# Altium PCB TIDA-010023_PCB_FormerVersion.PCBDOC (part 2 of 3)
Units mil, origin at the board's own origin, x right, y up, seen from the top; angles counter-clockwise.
Board outline 4724.44 x 3937.01 mil, 2 copper layers (Top Layer, Bottom Layer), stack 62 mil thick; 263 components, 126 nets, 611 pads, 186 vias.
Unrouted connection lines stored in the file: 58.
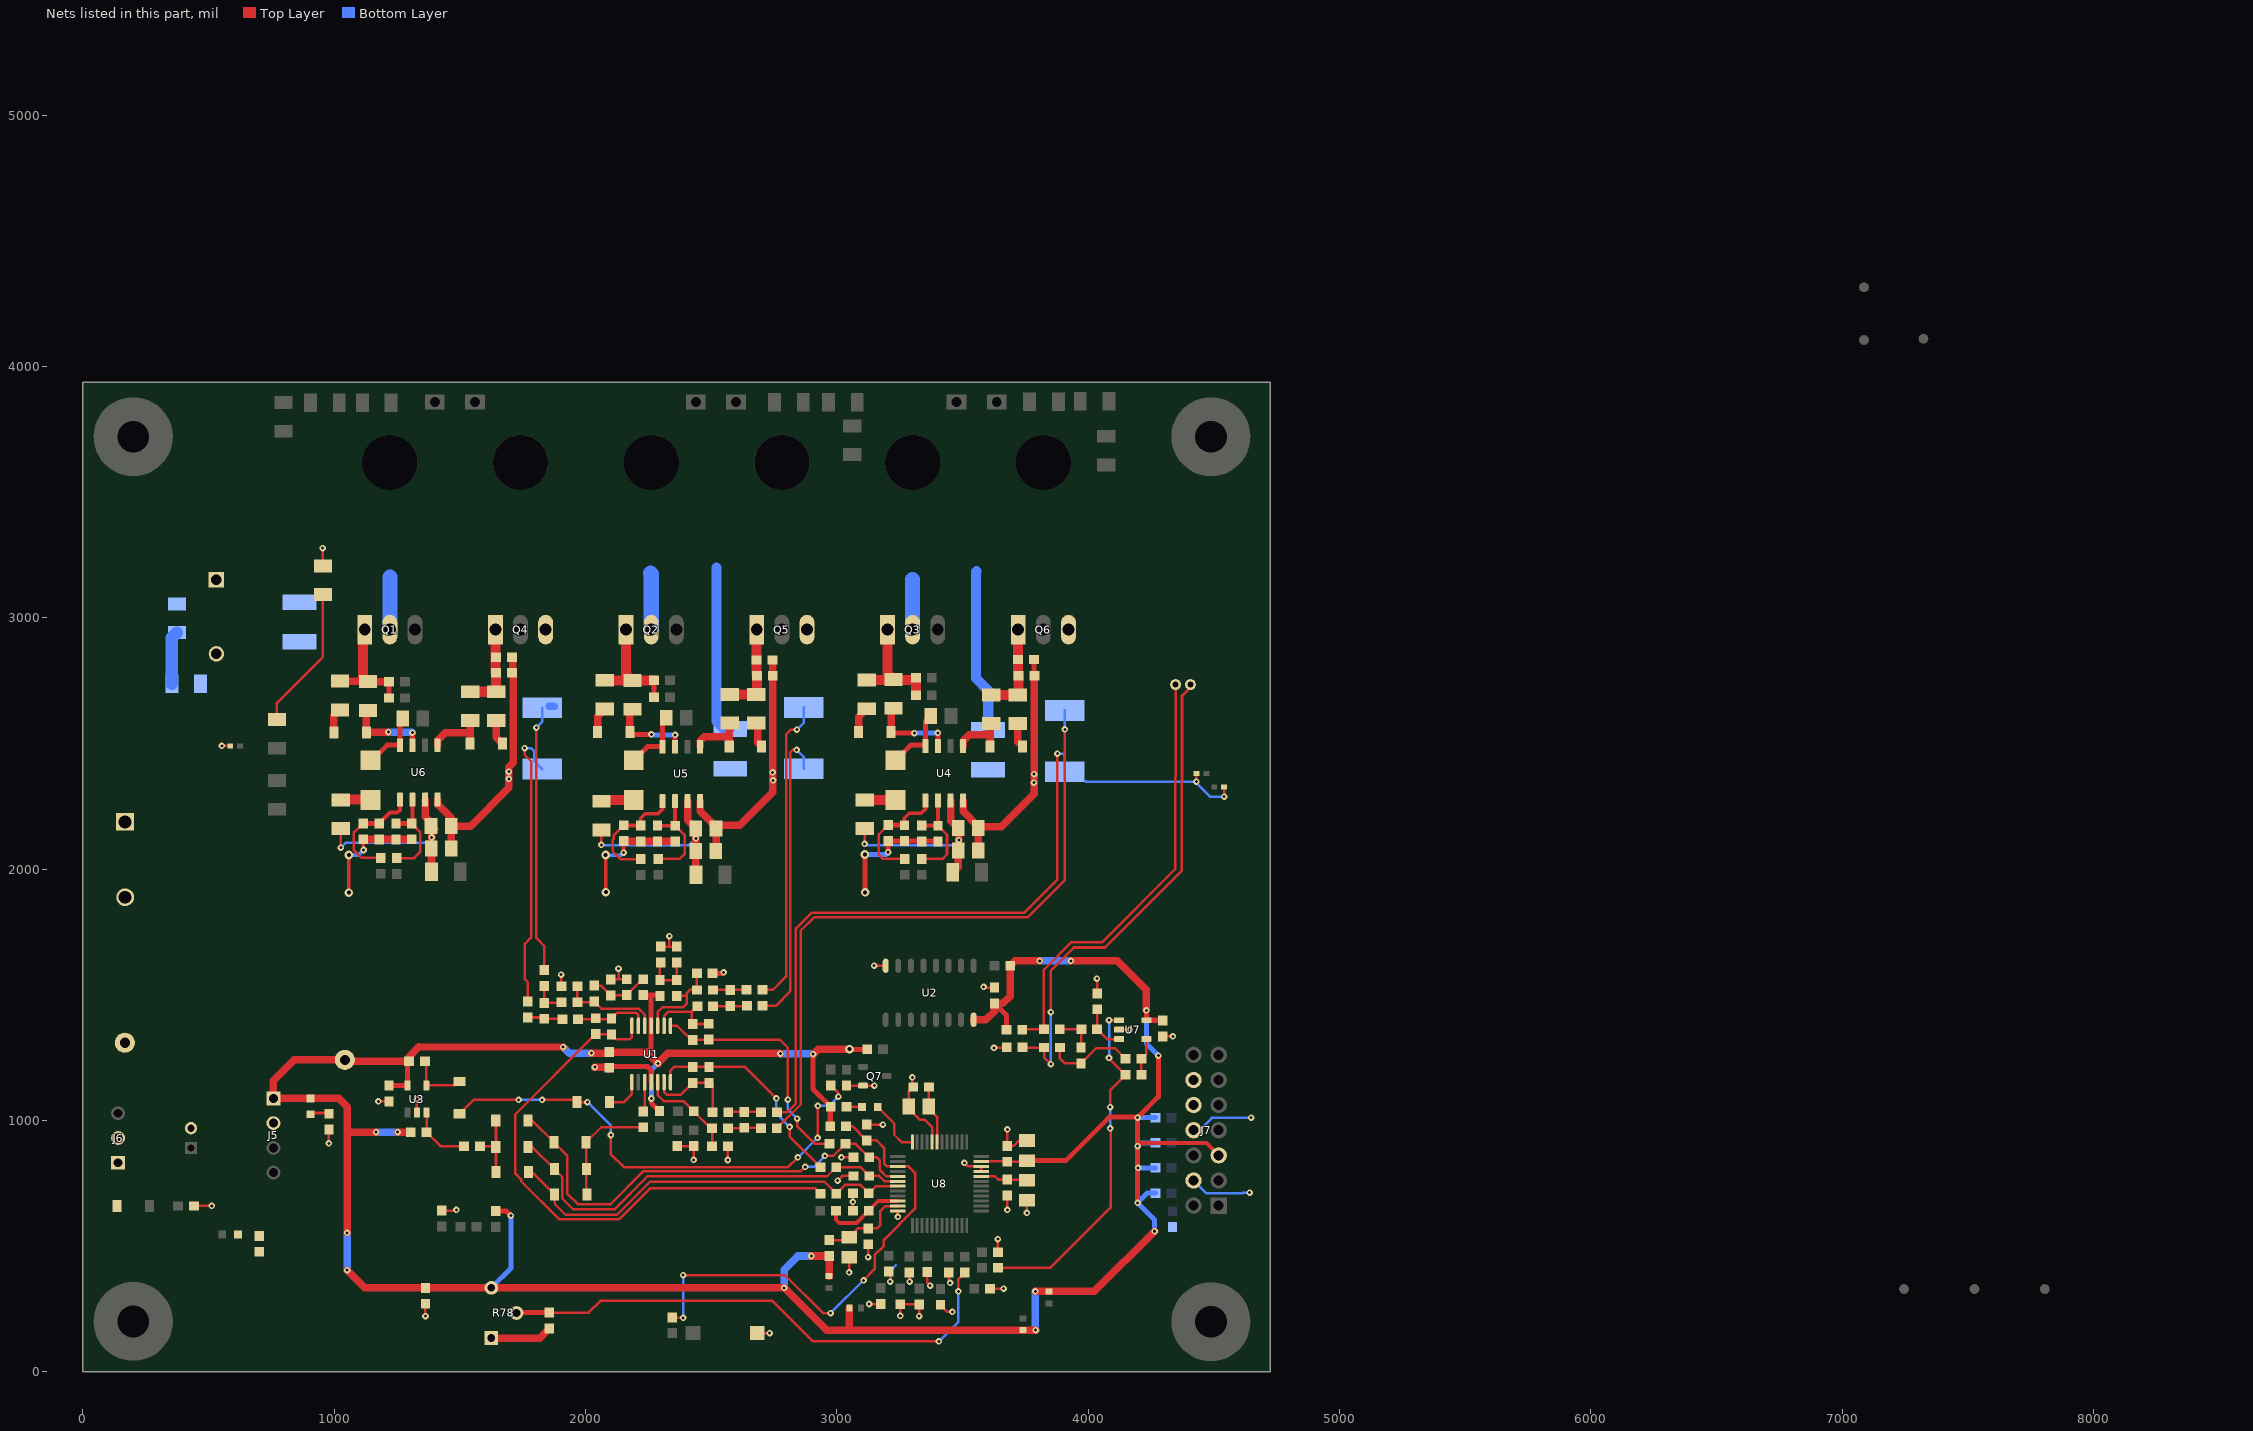
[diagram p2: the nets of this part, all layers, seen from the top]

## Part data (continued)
H1 H2 H3 H4: "Machine Screw, Round, #4-40 x 1/4, Nylon, Philips panhead", DigiKeyPartNumber=H542-ND, Manufacturer="B&F Fastener Supply"
H11 H12 H13 H14: "Standoff, Hex, 0.5\"L #4-40 Nylon", Alternate Manufacturer=-, Manufacturer=Keystone, Supplier Part Number 1=1902CK-ND
J1 J2 J3: "Header, 3.96 mm, 2x1, Tin, TH", Manufacturer="JST Manufacturing", Supplier Part Number 1=455-1639-ND
J4: library part 1707027, "TERMINAL BLOCK 7.50MM 2POS PCB", Color=Green, Current_A=16, Manufacturer="On Shore Technology Inc.", Supplier Part Number 1=ED2730-ND, Voltage_V=1000
J5: "Header (Shrouded), 2.5mm, 4x1, Tin, TH", Color=White, Current_A=3, Manufacturer="JST Manufacturing", Supplier Part Number 1=455-2249-ND, Voltage_V=250
J6: library part B2B-XH-A(LF)(SN), "Header (Shrouded), 2.5mm, 2x1, Tin, TH", Color=White, Current_A=3, Manufacturer="JST Manufacturing", Supplier Part Number 1=455-2247-ND, Voltage_V=250
J7: "Header, 100mil, 7x2, Tin, TH", Color=Black, Current_A=3, Manufacturer="Sullins Connector Solutions", Supplier Part Number 1=S2012E-07-ND, Voltage_V=1800
Logo_TI: library part TI_Logo, "Texas Instrument Corporate Signature"
Pb: library part Pb-Free
Pb_Free: library part ESD_Susceptible, "ESD Susceptible Symbol"
Q1 Q2 Q3 Q4 Q5 Q6: library part "IXYP15N65C3D1, IXYS", "Transistor, IGBT, 650 V, 38 A, TO-220AB", Manufacturer=IXYS, PartNumber=IXYP15N65C3D1, Supplier Part Number 1=IXYP15N65C3D1-ND, Value1="38 A"
Q7: library part "MMBT2222A, Fairchild Semiconductor", "Transistor, NPN, 40 V, 0.15 A, SOT-23", Manufacturer="Fairchild Semiconductor", Supplier Part Number 1=MMBT2222AFSCT-ND, Value1="0.15 A", Value2=300
R1 R13 R23: "RES, 4.99 k, 0.1%, 0.1 W, 0603", Manufacturer="Yageo America", Power_W=0.1, TempCo="25 ppm/C", Value1=0.1%, Value2=0.1W, Value_Code=4k99, ValueDisplayed=1.91k
R2 R14 R24: "RES, 4.99 k, 0.1%, 0.1 W, 0603", Manufacturer="Yageo America", Power_W=0.1, TempCo="25 ppm/C", Value1=0.1%, Value2=0.1W, Value_Code=4k99, ValueDisplayed=2k
R3 R9 R15 R22 R25 R29: "RES, 4.99 k, 0.1%, 0.1 W, 0603", Manufacturer="Yageo America", Power_W=0.1, TempCo="25 ppm/C", Value1=0.1%, Value2=0.1W, Value_Code=4k99, ValueDisplayed=40.2k
R4 R16 R26 R120: "RES, 100, 1%, 0.1 W, 0603", Manufacturer=Vishay-Dale, Power_W=0.1, Supplier Part Number 1=541-100HCT-ND, TempCo="100 ppm/C", Tolerance_%=1, Value1=1%, Value2=0.1W, Value_Code=100R, ValueDisplayed=47
R5 R7 R17 R21 R27 R28: library part RG1608P-101-B-T5, "RES, 100, 0.1%, 0.1 W, 0603", Manufacturer="Susumu Co Ltd", Power_W=0.1, Supplier Part Number 1=RG16P100BCT-ND, TempCo="25 ppm/C", Value1=0.1%, Value2=0.1W, Value_Code=100R, ValueDisplayed=1.91k
R6 R11: "RES, 10.0 k, 1%, 0.1 W, 0603", Manufacturer=Vishay-Dale, Power_W=0.1, Supplier Part Number 1=541-10.0KHCT-ND, TempCo="100 ppm/C", Tolerance_%=1, Value1=1%, Value2=0.1W, Value_Code=10k0, ValueDisplayed=0
R8 R66 R68 R70 R74 R79 R87: "RES, 100, 1%, 0.1 W, 0603", Manufacturer=Vishay-Dale, Power_W=0.1, Supplier Part Number 1=541-100HCT-ND, TempCo="100 ppm/C", Tolerance_%=1, Value1=1%, Value2=0.1W, Value_Code=100R, ValueDisplayed=100
R10: "RES, 10.0 k, 1%, 0.1 W, 0603", Manufacturer=Vishay-Dale, Power_W=0.1, Supplier Part Number 1=541-10.0KHCT-ND, TempCo="100 ppm/C", Tolerance_%=1, Value1=1%, Value2=0.1W, Value_Code=10k0, ValueDisplayed=100k
R12 R118 R119: "RES, 10.0 k, 1%, 0.1 W, 0603", Manufacturer=Vishay-Dale, Power_W=0.1, Supplier Part Number 1=541-10.0KHCT-ND, TempCo="100 ppm/C", Tolerance_%=1, Value1=1%, Value2=0.1W, Value_Code=10k0, ValueDisplayed=10k
R18 R63: "RES, 10.0 k, 1%, 0.1 W, 0603", Manufacturer=Vishay-Dale, Power_W=0.1, Supplier Part Number 1=541-10.0KHCT-ND, TempCo="100 ppm/C", Tolerance_%=1, Value1=1%, Value2=0.1W, Value_Code=10k0, ValueDisplayed=10.0k
R19: "RES, 21.5 k, 1%, 0.1 W, 0603", Manufacturer=Vishay-Dale, Power_W=0.1, Supplier Part Number 1=541-21.5KHCT-ND, TempCo="100 ppm/C", Tolerance_%=1, Value1=1%, Value2=0.1W, Value_Code=21k5, ValueDisplayed=21.5k
R20: library part CRCW060321K5FKEA, "RES, 21.5 k, 1%, 0.1 W, 0603", Manufacturer=Vishay-Dale, Power_W=0.1, Supplier Part Number 1=541-21.5KHCT-ND, TempCo="100 ppm/C", Tolerance_%=1, Value1=1%, Value2=0.1W, Value_Code=21k5, ValueDisplayed=10.0k
R30 R40 R59: "RES, 3.3 ohm, 5%, 0.25W, 1206", Manufacturer=Vishay-Dale, Power_W=0.25, Supplier Part Number 1=541-3.3ECT-ND, TempCo="200 ppm/C", Tolerance_%=5, Value1=5%, Value2=0.25W, Value_Code=3R30
R31 R41 R57 R60 R75: "RES, 12.0, 1%, 0.25 W, 1206", Manufacturer="Yageo America", Power_W=0.25, Supplier Part Number 1=311-12.0FRCT-ND, TempCo="100 ppm/C", Tolerance_%=1, Value1=1%, Value2=0.25W, Value_Code=12R0, ValueDisplayed=12.0
R32 R42 R61: "RES, 2.2, 1%, 0.1 W, 0603", Manufacturer="Yageo America", Power_W=0.1, Supplier Part Number 1=311-5.11HRCT-ND, TempCo="200 ppm/C", Tolerance_%=1, Value1=1%, Value2=0.1W, Value_Code=5R11, ValueDisplayed=2.2
R33 R37 R45 R55 R62 R72: "RES, 5, 1%, 0.25 W, 1206", Manufacturer=Vishay-Dale, Power_W=0.25, Supplier Part Number 1=541-6.04FFCT-ND, TempCo="100 ppm/C", Tolerance_%=1, Value1=1%, Value2=0.25W, Value_Code=6R04, ValueDisplayed=5.00
R34 R39 R49 R58 R64 R76: "RES, 20.0k ohm, 1%, 0.1W, 0603", Manufacturer=Vishay-Dale, Power_W=0.1, Supplier Part Number 1=541-20.0KHCT-ND, TempCo="100 ppm/C", Tolerance_%=1, Value1=1%, Value2=0.1W, Value_Code=20k0
R35 R36 R50 R54 R65 R71: "RES, 51.1, 1%, 0.1 W, 0603", Manufacturer=Vishay-Dale, Power_W=0.1, Supplier Part Number 1=541-51.1HCT-ND, TempCo="100 ppm/C", Tolerance_%=1, Value1=1%, Value2=0.1W, Value_Code=51R1, ValueDisplayed=49.9
R38: "RES, 12.0, 1%, 0.25 W, 1206", Manufacturer="Yageo America", Power_W=0.25, Supplier Part Number 1=311-12.0FRCT-ND, TempCo="100 ppm/C", Tolerance_%=1, Value1=1%, Value2=0.25W, Value_Code=12R0, ValueDisplayed=12.00
R43 R46 R47 R51 R53 R56: "RES, 0, 5%, 0.1 W, 0603", Manufacturer=Vishay-Dale, Power_W=0.1, Supplier Part Number 1=541-0.0GCT-ND, TempCo="200 ppm/C", Tolerance_%=5, Value1=5%, Value2=0.1W, Value_Code=0000, ValueDisplayed=100
R44 R48 R52: "RES, 0.005, 1%, 3 W, AEC-Q200 Grade 0, 2512", Manufacturer=Bourns, Power_W=3, Supplier Part Number 1=CRE2512-FZ-R005E-3CT-ND, TempCo="75 ppm/C", Tolerance_%=1, Value1=1%, Value2=3W, Value_Code=5L000, ValueDisplayed=0.005
R67 R69: "RES, 1.00 k, 1%, 0.1 W, 0603", Manufacturer=Vishay-Dale, Power_W=0.1, Supplier Part Number 1=541-1.00KHCT-ND, TempCo="100 ppm/C", Tolerance_%=1, Value1=1%, Value2=0.1W, Value_Code=1k00, ValueDisplayed=1.91k
R73 R77: "RES, 1.00 k, 1%, 0.1 W, 0603", Manufacturer=Vishay-Dale, Power_W=0.1, Supplier Part Number 1=541-1.00KHCT-ND, TempCo="100 ppm/C", Tolerance_%=1, Value1=1%, Value2=0.1W, Value_Code=1k00, ValueDisplayed=2.55k
R78: "TRIMMER, 20k ohm, 0.5W, TH", Manufacturer=Bourns, Supplier Part Number 1=3386P-203LF-ND
R80 R83: "RES, 300 k, 5%, 0.25 W, 1206", Manufacturer=Vishay-Dale, Power_W=0.25, Supplier Part Number 1=541-300KECT-ND, TempCo="200 ppm/C", Tolerance_%=5, Value1=5%, Value2=0.25W, Value_Code=300k
R81: "RES, 1.00 M, 1%, 0.1 W, 0603", Manufacturer=Vishay-Dale, Power_W=0.1, Supplier Part Number 1=541-1.00MHCT-ND, TempCo="100 ppm/C", Tolerance_%=1, Value1=1%, Value2=0.1W, Value_Code=1M00, ValueDisplayed=1.00M
R82 R85: "RES, 1.00 k, 1%, 0.1 W, 0603", Manufacturer=Vishay-Dale, Power_W=0.1, Supplier Part Number 1=541-1.00KHCT-ND, TempCo="100 ppm/C", Tolerance_%=1, Value1=1%, Value2=0.1W, Value_Code=1k00, ValueDisplayed=1.00k
R84: "RES, 4.99 k, 1%, 0.1 W, 0603", Manufacturer=Bourns, Power_W=0.1, Supplier Part Number 1=CR0603-FX-4991ELFTR-ND, TempCo="100 ppm/C", Tolerance_%=1, Value1=1%, Value2=0.1W, Value_Code=4k99, ValueDisplayed=4.99k
R86 R99 R100 R101 R102 R103: "RES, 4.7 k, 5%, 0.1 W, 0603", Manufacturer=Vishay-Dale, Power_W=0.1, Supplier Part Number 1=541-4.7KGCT-ND, TempCo="200 ppm/C", Tolerance_%=5, Value1=5%, Value2=0.1W, Value_Code=4k70, ValueDisplayed=4.7k
R88: "RES, 0, 5%, 0.1 W, 0603", Manufacturer=Vishay-Dale, Power_W=0.1, Supplier Part Number 1=541-0.0GCT-ND, TempCo="200 ppm/C", Tolerance_%=5, Value1=5%, Value2=0.1W, Value_Code=0000, ValueDisplayed=0
R91 R92 R93 R94 R95 R96 R97 R98 R104 R105 R106 R107: "RES, 374 k, 1%, 0.25 W, 1206", Manufacturer="Yageo America", Power_W=0.25, Supplier Part Number 1=311-374KFRCT-ND, TempCo="100 ppm/C", Tolerance_%=1, Value1=1%, Value2=0.25W, Value_Code=374k
R108 R109 R110 R111: "RES, 9.09 k, 1%, 0.1 W, 0603", Manufacturer=Vishay-Dale, Power_W=0.1, Supplier Part Number 1=541-9.09KHCT-ND, TempCo="100 ppm/C", Tolerance_%=1, Value1=1%, Value2=0.1W, Value_Code=9k09, ValueDisplayed=9.09k
R112 R113 R114 R115 R116 R117: "RES, 51.1, 1%, 0.1 W, 0603", Manufacturer=Vishay-Dale, Power_W=0.1, Supplier Part Number 1=541-51.1HCT-ND, TempCo="100 ppm/C", Tolerance_%=1, Value1=1%, Value2=0.1W, Value_Code=51R1, ValueDisplayed=10k
RT1: library part NTCALUG03A103G, "Thermistor NTC, 10k ohm, 2%, NTC Thermistor, Mini Lug Sensor, Pitch 1.5mm", Manufacturer=Vishay-Bccomponents, Power_W=0.1, Supplier Part Number 1=BC2385-ND, Tolerance_%=2
S1: "Switch, Tactile, SPST, 12 V, SMD", CurrentRating_mA=50, Manufacturer="Wurth Elektronik", Supplier Part Number 1=1867991
TP1 TP2: "Test Point, Miniature, Red, TH", Color=Red, Manufacturer=Keystone, Supplier Part Number 1=36-5000-ND
U1: library part TLV2774AID, "Quad High-Slew-Rate Rail-to-Rail Output Operational Amplifier, 2.5 to 6 V, -40 to 125 degC, 14-pin SOIC (D0014A), Green (RoHS & no Sb/Br)", Alternate Manufacturer="Texas Instruments", Alternate PartNumber=Equivalent, PartNumber=TLV2774AIDA, Rating=Catalog, Total Supply Voltage(Max)(+5V is 5, +/-5V is 10)=6, Total Supply Voltage(Min)(+5V is 5, +/-5V is 10)=2.5
U2: "Hex Buffers And Line Drivers With 3-State Outputs, D0016A, LARGE T&R", Alternate Manufacturer="Texas Instruments", Alternate PartNumber=Equivalent, F @ Nom Voltage(Max)(Mhz)=110, Generic Part Number=SN74AHC367, ICC @ Nom Voltage(Max)(mA)=0.04, Operating Temperature Range(C)="-40 to 85", Rating=Catalog, tpd @ Nom Voltage(Max)(ns)=12.5,8.5, Voltage(Nom)(V)=3.3,5
U3: "2.2-V to 36-V, microPower Comparator, DBV0005A", Alternate Manufacturer="Texas Instruments", Alternate PartNumber=TLV1701AIDBVT
U4 U5 U6: "620-V High-Side Low-Side Gate Driver with 2.5A Peak Output and RobustDrive, D0008B (SOIC-8)", Alternate Manufacturer="Texas Instruments", Alternate PartNumber=UCC27712D
U7: library part LMV721IDBV, "1-MHz, Low-Power Operational Amplifier", Alternate Manufacturer="Texas Instruments", PartNumber=TLV6001IDBVT
U8: library part TMS320F2802XPTA, "IC, 32-Bit Piccolo Microcontrollers, xx MHz", Alternate Manufacturer=None, Manufacturer=TI, PartNumber=TMS320F28027FPTT
U9 U10 U11: "ESD in 0402 Package with 10 pF Capacitance and 6 V Breakdown, 1 Channel, -40 to +125 degC, 2-pin X2SON (DPY), Green (RoHS & no Sb/Br)", Alternate Manufacturer="Texas Instruments", Alternate PartNumber=Equivalent, Breakdown Voltage(Min)(V)=6, IO Capacitance(Typ)(pF)=10, Supplier Part Number 1=296-30406-2-ND
ZZ1: library part AssemblyNoteLabel, Alternate Manufacturer=-
ZZ2 ZZ3 ZZ4: library part AssemblyNote, Alternate Manufacturer=-

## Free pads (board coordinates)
  round 220 hole 220: 1(1221.18,3617.91) 1(1741.18,3617.91) 1(2261.18,3617.91) 1(2781.18,3617.91) 1(3301.18,3617.91) 1(3821.18,3617.91)

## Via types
v1: diameter 26, hole 12, Top Layer to Bottom Layer, 157 vias
v2: diameter 34, hole 16, Top Layer to Bottom Layer, 28 vias
v3: diameter 32, hole 18, Top Layer to Bottom Layer, 1 vias

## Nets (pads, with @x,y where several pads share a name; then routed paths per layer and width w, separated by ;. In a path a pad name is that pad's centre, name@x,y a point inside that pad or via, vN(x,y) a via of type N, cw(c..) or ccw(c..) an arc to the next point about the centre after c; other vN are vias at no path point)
+3.3VD: C1.1 C2.2 C8.1 C39.1 C49.2 C52.1 C53.1 D19.2 D22.1 D23.1 D24.1 D25.1 J5.1 J7.5 R1.2 R10.1 R12.2 R13.2 R18.2 R23.2 R63.1 R78.3 R82.2 R86.2 R88.2 R99.2 R100.2 R101.2 R102.2 R118.1 R119.1 TP2.1 U1.4 U2.16 U3.5 U7.5 U8.35 | length 12718.7
  Top Layer w10: U8.35@3574.1,836.7 3676.8,836.7 C52.1@3678,835.5 3751.5,835.5 C53.1@3756,840
  Top Layer w15: v1(4196,898) 4208,910 4470,910 J7.5@4519,861
  Top Layer w20: C8.1@1218,1138.5 1290.96,1138.5 U3.5@1291.6,1139.13 1291.6,1230.09 R12.2@1297.5,1236 ; R18.2@1643,639.5 1684.5,639.5 v1(1703,621) ; C1.1@2101.64,1277.42 C1.1@2103,1277.42 ; R1.2@2228.98,1498.7 2263,1498.7 ; 2243.5,1270.5 2260.98,1287.97 U1.4@2260.98,1376.4 2260.98,1496.69 2263,1498.7 ; v1(2261.98,1087.2) 2261.98,1068.7 R23.2@2293.98,1036.7 ; R13.2@2295.98,1495.7 2292.98,1498.7 2263,1498.7 ; v1(2905,1264) 2905,1124.5 R82.2@2975.5,1054 2973.5,1052 R86.2@2973.5,977 ; v2(3050,1284) 3051,1283 R119.1@3120.5,1283 R119.1@3119.5,1284 ; C2.2@3627,1465.5 3674.5,1418 R63.1@3674.5,1361 R63.1@3673.79,1361.72 ; C53.1@3756,840 3910,840 4083,1013 4194,1013 v1(4196,1011) ; v1(4196,672) v1(4196,898) v1(4196,1011) ; v1(4231,1438) 4231.13,1437.87 U7.5@4231.13,1398.6 4294.9,1398.6 C39.1@4296,1397.5 ; v1(4279,1258) 4279,1094 v1(4196,1011)
  Top Layer w30: D19.2@902.14,1087.64 J5.1@758,1087.64 758,1158 841,1241 TP2.1@1042,1241 1047,1236 R12.2@1297.5,1236 1297.5,1253.5 1337,1293 v1(1911,1292) ; D19.2@905,1087.5 1017.5,1087.5 1051,1054 1051,958 ; v1(1051,404) 1121,334 R78.3@1625,334 v1(2790,334) 2959,165 3055,165 ; v1(1051,553) 1051,905 ; 1051,905.5 1051,958 ; v1(1167,953) 1056,953 1051,958 ; v1(1252,953) R10.1@1304.5,953 ; v1(2023.35,1268) 2100.5,1268 2103,1270.5 2243.5,1270.5 v1@2289,1225 ; v1(2287.98,1227.2) 2327.78,1267 2774,1267 v1(2775,1266) ; v1(2898.5,460.5) R88.2@2969,460.5 D22.1@2969,380.24 ; v1(2905,1264) 2925,1284 v2(3050,1284) ; D25.1@3049.38,253 3049.38,176.62 3055,165 ; U2.16@3544,1400.72 3592.72,1400.72 3627,1435 C2.2@3627,1465.5 3660.5,1465.5 3689.5,1494.5 R118.1@3689.5,1615 3709.5,1635 v1(3807,1635) ; D23.1@3735.38,165 3055,165 ; D23.1@3741,165.38 3790.38,165.38 v1(3791,166) ; v1(3789.62,319.62) D24.1@3844,319.62 4024.62,319.62 v1(4264,559) ; v1(3931,1635) 4116,1635 4231,1520 v1(4231,1438)
  Bottom Layer w20: R78.3@1625,334 1703,412 v1(1703,621) ; v1(2261.98,1087.2) 2261.98,1201.2 v1(2287.98,1227.2) ; v1(4196,898) 4209,911 R101.2@4267.9,911 ; v1(4196,1011) R102.2@4267.9,1011 ; v1(4198,811) R100.2@4267.9,811 ; v1(4231,1438) 4231,1306 v1(4279,1258) ; v1(4264,559) 4264,604 v1(4196,672) 4235,711 R99.2@4267.9,711
  Bottom Layer w30: v1(1051,404) v1(1051,553) ; v1(1167,953) v1(1252,953) ; v1(1911,1292) 1935,1268 v1(2023.35,1268) ; v1(2775,1266) 2903,1266 v1(2905,1264) ; v1(2790,334) 2790,406 2844.5,460.5 v1(2898.5,460.5) ; v1(3789.62,319.62) 3789.62,167.38 v1(3791,166) ; v1(3807,1635) v1(3931,1635)
+VDC: C24.1 C25.1 C26.1 C50.1 J4.1 Q1.2 Q2.2 Q3.2 R80.2 R91.2 | length 2040.8
  Top Layer w10: v1(954,3277) 955,3276 R91.2@955,3206.09
  Bottom Layer w40: 2521,3200 2521,2588 2548.79,2560.21 2571.53,2560.21 C25.1@2575,2556.74 ; 3555,3186 3553,3184 3553,2759 3602,2710 3602,2553.74 C26.1@3601,2552.74
  Bottom Layer w60: Q1.2@1221.18,2952.76 1221.03,3162.01 1221.18,3161.86 1221.52,3161.52 ; 2258,3178 2261.18,3174.82 Q2.2@2261.18,2952.76 ; 3300.23,3152 3300.23,3090.06 Q3.2@3301.18,2952.76
A_BOT: C46.1 Q4.1 R72.2 R75.2 R76.2 | length 352.6
  Top Layer w40: R72.2@1540.68,2705.59 R75.2@1644.68,2705.59 1644.19,2706.08 R76.2@1644.19,2780.5 1641.18,2783.51 Q4.1@1641.18,2952.76
A_TOP: C40.1 Q1.1 R60.2 R62.2 R64.2 | length 456.6
  Top Layer w20: 1217.87,2725.06 1218.5,2725.7 ; R64.2@1218.5,2680.7 1218.5,2725.7 ; C40.1@1218.5,2745.7 1218.5,2725.7
  Top Layer w30: R60.2@1023,2747.77 1115,2747.77 1132,2747.77 R62.2@1134,2745.77 C40.1@1204.57,2745.77
  Top Layer w40: R62.2@1115,2747 1115,2747.77 1115,2946.57 Q1.1@1121.18,2952.76
AGND: C1.2 C2.1 C4.1 C5.2 C7.2 C8.2 C9.2 C12.2 C13.2 C15.2 C18.2 C19.2 C21.2 C23.1 C24.2 C25.2 C26.2 C29.2 C30.2 C31.2 C32.1 C35.2 C36.2 C37.2 C38.1 C39.2 C42.2 C44.1 C45.2 C46.2 C47.1 C48.1 C49.1 C50.2 C51.1 C52.2 C53.2 C54.2 C55.2 C56.2 C57.2 C58.2 C59.2 C60.2 C61.2 C62.2 C63.2 C64.2 C65.1 C66.1 C67.1 C68.2 J4.2 J5.2 J6.2 J7.4 J7.8 J7.10 J7.12 Q7.2 R2.1 R14.1 R20.1 R24.1 R39.1 R44.2 R47.1 R48.2 R52.2 R53.2 R56.1 R58.1 R73.2 R74.2 R76.1 R78.1 R81.1 R83.1 R84.1 R85.1 R103.2 R108.1 R109.1 R110.1 R111.1 R112.2 R113.2 R114.2 R115.2 R116.2 R117.2 S1.2 TP1.1 U1.11 U2.8 U3.2 U4.4 U5.4 U6.4 U7.2 U8.12 U8.33 U8.34 U8.44 U9.2 U10.2 U11.2 | length 14038.7
  Top Layer w10: C60.2@441.5,659.61 v1(512.61,659.61) ; v1(553,2490) U9.2@586.32,2490 ; v1(979,909) R85.1@979,963.5 ; v1(1175.5,1075.5) C8.2@1218,1075.5 ; U3.2@1329,1030.87 v1(1329,1085) ; v1(1363,221) C49.1@1363,270.5 ; R20.1@1428,641.5 1483.5,641.5 v1(1486,644) ; v1(1757.12,2481) 1757.12,2454.88 1783,2429 1783,1727 1758,1702 1758,1562 1770,1550 R47.1@1770,1472.5 ; v1(1903,1580) 1903,1535.5 C7.2@1904.5,1534 ; R2.1@2100,1560.5 2101,1561.5 2135.8,1561.5 ; v1(2131,1604) 2131,1566.3 2135.8,1561.5 ; C4.1@2163,1561.5 2135.8,1561.5 ; C12.2@2299,1691.5 2335.8,1691.5 ; v1(2333,1733) 2333,1694.3 2335.8,1691.5 ; R14.1@2361,1693.5 R14.1@2363,1691.5 2335.8,1691.5 ; C18.2@2364.98,897.7 R24.1@2429.98,897.7 v1(2429.98,842.98) ; v1(2566.48,842.48) C21.2@2566.48,897.2 ; S1.2@2682.95,154 v1(2732,154) ; R56.1@2704.5,1456 2757,1456 2814,1513 2814,2464 2824,2474 v1(2840,2474) ; R53.2@2761.5,1033 2803,1033 2837,1067 2837,1764 2899,1826 3745,1826 3877,1958 v1(3877,2459) ; v1(3003,760) 3022,779 C19.2@3065.5,779 ; v1(3018,853) C13.2@3065.5,853 ; C9.2@3038,1138.5 3103.66,1138.5 Q7.2@3103.76,1138.6 v1(3148.6,1138.6) ; v1(3049,395) C57.2@3049,456 ; C68.2@3063.5,641 v1(3063.5,675.5) C5.2@3063.5,710 ; C54.2@3118,983.5 v1(3182.5,983.5) ; v1(3124,456) C58.2@3124,507.5 ; v1(3128.5,269.5) R108.1@3174,269.5 ; v1(3148,1616) 3148.72,1615.28 U2.8@3194,1615.28 ; C61.2@3207,398.5 3212,403.5 v1(3212,359) ; v1(3242.1,616.1) U8.12@3242.1,639.7 ; v1(3252,222) R111.1@3252,268.5 3326,268.5 R109.1@3327,267.5 v1(3327,221) ; C64.2@3287,395.5 3279.2,387.7 3289.7,377.2 v1(3289.7,358.45) ; v1(3300,1171) 3300,1136.5 C48.1@3303.5,1133 3286,1115.5 C47.1@3286,1055 3286,1047 3331,1002 3350,1002 3378.6,973.4 U8.44@3378.6,913.9 ; C62.2@3360,396.5 3360,354 v1(3371,343) ; R110.1@3412,266.5 3440.5,238 v1(3459,238) ; C63.2@3445,394.5 3445,359 v1(3450,354) ; v1(3507,831) 3521,817 U8.34@3574.1,817 U8.33@3574.1,797.3 ; v1(3584,1531) 3586.5,1528.5 C2.1@3627,1528.5 ; C51.1@3609.5,331 v1(3663,331) ; v1(3625,1289) 3673.5,1289 R74.2@3675.5,1291 ; C44.1@3640.5,475 v1(3640.5,527.5) ; v1(3678,644) C56.2@3678,701.5 ; v1(3678,964) C52.2@3678,898.5 3703.5,898.5 3725,920 C53.2@3756,920 ; v1(3756,632) C55.2@3756,682 ; v1(4034,1564) 4036,1562 R73.2@4036,1505.5 ; U7.2@4122.86,1361.19 v1(4165.81,1361.19) ; C39.2@4296,1334.5 v1(4336.5,1334.5) ; v1(4430.31,2348.32) U10.2@4430.31,2381 ; v1(4540.69,2288.32) U11.2@4540.69,2326
  Top Layer w15: v2(1058,1906) v2(1058,2056) ; R116.2@1115,2118.5 1115,2078 v1(1117,2076) ; v2(2080,2056) 2080,1909 v2(2081,1908) ; v1(2151.3,2065.7) R114.2@2151.3,2111.5
  Top Layer w20: C1.2@2101.64,1214.42 2246.58,1214.42 2260.98,1200.02 U1.11@2260.98,1152 ; C15.2@2505.5,1585 2545,1585 v1(2549,1589) ; v2(3111,2058) 3111,1908 v2(3112,1907) ; v1(3204,2067) R112.2@3204,2112.5 3399,2112.5 C30.2@3402,2109.5 ; C31.2@3783.5,2772 R39.1@3783.5,2834
  Top Layer w30: R116.2@1115,2118.5 1178.12,2118.5 C42.2@1178.52,2118.11 C45.2@1245.52,2118.11 1307.6,2118.11 R117.2@1308,2118.5 ; U6.4@1411.52,2276.34 1411.52,2258.48 1465.52,2204.48 C67.1@1465.52,2171 ; C67.1@1465,2171 C67.1@1465.52,2171 ; C38.1@1467,2095 1465.52,2096.48 C67.1@1465.52,2171 ; R78.1@1625,134 1816.89,134 R81.1@1855,172.11 ; R76.1@1707.18,2780.5 1712,2775.68 1712,2423 1695,2406 v1(1695,2388) v1(1695,2359) 1695,2323 1543,2171 C67.1@1465.52,2171 ; R76.1@1709.68,2780.5 C46.2@1709.68,2834.41 ; v1(2037,1212) 2083.61,1212 C1.2@2091.41,1204.2 ; R114.2@2151.3,2111.5 2285.3,2111.5 R115.2@2286.3,2110.5 2356.3,2110.5 C36.2@2357.3,2109.5 ; U5.4@2456,2270.34 2456,2231 2472.5,2214.5 2472.7,2214.5 2512.2,2175 C66.1@2519,2175 ; C32.1@2518,2072 2519,2073 C66.1@2519,2162 C66.1@2519,2175 ; R58.1@2743.5,2832 2744.5,2831 C37.2@2744.5,2769 v1(2744.5,2385) 2744.5,2305.5 2614,2175 C66.1@2519,2175 ; U4.4@3502,2272.73 3502,2229.2 C65.1@3562,2169.2 ; C23.1@3562,2074 C65.1@3562,2163 C65.1@3562,2169.2 ; C31.2@3783.5,2772 3785,2770.5 v1(3785,2378) 3785,2300 3654.2,2169.2 C65.1@3562,2169.2
  Bottom Layer w10: v1(1757.12,2481) 1782,2481 1796,2467 1796,2428.95 R44.2@1827,2397.95 ; v1(2840,2474) 2868,2446 R52.2@2868,2398.95 ; v1(3212,359) 3212,401.51 3234,423.51 ; v1(3877,2459) 3899,2459 3907,2451 R48.2@3907,2386.95 ; 3989,2350 3990.69,2348.32 v1(4430.31,2348.32) 4430.31,2341.68 4483.69,2288.32 v1(4540.69,2288.32) ; J7.4@4419,761 4469,711 4614,711 4616,713 v1(4642,713) ; J7.8@4419,961 4443,961 4492,1010 4647,1010 v1(4648,1011)
  Bottom Layer w15: v2(1058,2056) 1097,2056 v1(1117,2076) ; v2(2080,2056) 2081,2055 2140.6,2055 v1(2151.3,2065.7)
  Bottom Layer w20: v2(3111,2058) 3195,2058 v1(3204,2067)
  other v1: 3784,2344 2746,2353
B_BOT: C37.1 Q5.1 R55.2 R57.2 R58.2 | length 363.8
  Top Layer w40: R55.2@2581,2695.09 R57.2@2679,2695.09 2685,2695.09 2681.5,2698.58 C37.1@2681.5,2769 2680.5,2770 R58.2@2680.5,2832 2680.5,2952.08 Q5.1@2681.18,2952.76
B_TOP: C33.1 Q2.1 R41.2 R45.2 R49.2 | length 477.9
  Top Layer w20: C33.1@2272.5,2683 R49.2@2272.5,2751
  Top Layer w40: R41.2@2076,2751.09 2076.09,2751 R45.2@2186.09,2751 ; Q2.1@2161.18,2952.76 2161.18,2775.91 R45.2@2186.09,2751 ; R45.2@2187,2750.09 R45.2@2186.09,2751 ; R49.2@2272.5,2751 R45.2@2186.09,2751
C_BOT: C31.1 Q6.1 R37.2 R38.2 R39.2 | length 368.7
  Top Layer w40: R37.2@3619,2693.09 R38.2@3719,2693.09 3726,2693.09 3722.5,2696.58 C31.1@3722.5,2770 3721.18,2771.32 Q6.1@3721.18,2952.76
C_TOP: C27.1 Q3.1 R31.2 R33.2 R34.2 | length 471.5
  Top Layer w40: R31.2@3119,2752.09 C27.1@3305.59,2752.09 ; Q3.1@3201.18,2952.76 3201.18,2777.91 R33.2@3225,2754.09 ; R34.2@3314.5,2692 3314.5,2743.17 C27.1@3305.59,2752.09 ; C27.1@3314.5,2761 C27.1@3305.59,2752.09
IA_FB: C5.1 D1.2 D5.1 R4.2 U8.7 | length 1676.7
  Top Layer w10: D5.1@1772.47,794 1787.53,794 D1.2@1876.53,705 1876.53,668.47 1921,624 2124,624 2256,756 2950.5,756 R4.2@2997.5,709 3033.5,745 3091.5,745 C5.1@3126.5,710 3154.7,738.2 U8.7@3242.1,738.2
IA_N: C6.1 R5.1 R47.2 | length 137.6
  Top Layer w10: R47.2@1770,1409.5 1831,1409.5 C6.1@1836,1404.5 1902,1404.5 R5.1@1904.5,1402
IA_P: C6.2 R7.1 R43.2 | length 138
  Top Layer w10: R43.2@1835,1535.5 1836,1534.5 C6.2@1836,1467.5 1902,1467.5 R7.1@1904.5,1470
IB_FB: C13.1 D3.2 D6.1 R16.2 U8.5 | length 1872
  Top Layer w10: D6.1@1771.47,1000 1786.53,1000 D3.2@1873.53,913 1928,858.53 1928,708 1969,667 2100,667 2231,798 2857,798 v1(2874,815) ; v1(2952,859) 2985.5,859 R16.2@3033.5,907 3074.5,907 C13.1@3128.5,853 3159,853 3171,841 3171,803 3196.4,777.6 U8.5@3242.1,777.6
  Bottom Layer w10: v1(2874,815) 2908,815 v1(2952,859)
IB_N: C14.1 R17.1 R56.2 | length 134.4
  Top Layer w10: R17.1@2507.5,1455 2640.5,1455 R56.2@2641.5,1456
IB_P: C14.2 R21.1 R51.2 | length 134.4
  Top Layer w10: R21.1@2506.5,1519 2639.5,1519 R51.2@2640.5,1520
IC_FB: C19.1 D4.2 D8.1 R26.2 U8.6 | length 1716.1
  Top Layer w10: D8.1@1771.47,895 1786.53,895 D4.2@1875.53,806 1907,774.53 1907,690 1951,646 2115,646 2247,778 2961.5,778 R26.2@2997.5,814 3093.5,814 C19.1@3128.5,779 3168,779 3189.1,757.9 U8.6@3242.1,757.9
IC_N: C20.2 R27.1 R53.1 | length 131.5
  Top Layer w10: R27.1@2567.48,1033.2 2567.97,1033.7 C20.2@2631.98,1033.7 2697.81,1033.7 R53.1@2698.5,1033
IC_P: C20.1 R28.1 R46.1 | length 132.8
  Top Layer w10: R28.1@2566.48,968.2 2629.48,968.2 C20.1@2631.98,970.7 2695.8,970.7 R46.1@2697.5,969
NetC4_2: C4.2 R1.1 R2.2 R3.1 | length 248.3
  Top Layer w10: R3.1@2035,1536.5 2061.01,1536.5 R2.2@2100,1497.5 2162,1497.5 C4.2@2163,1498.5 2226.19,1561.7 R1.1@2228.98,1561.7 2220.97,1569.7 R1.1@2220.77,1569.5
NetC7_1: C7.1 R3.2 R7.2 U1.5 | length 400.2
  Top Layer w10: C7.1@1967.5,1534 R7.2@1967.5,1470 2031.5,1470 R3.2@2035,1473.5 2035,1472.28 2062.27,1445.02 2210.98,1445.02 2235.39,1420.61 U1.5@2235.39,1376.4
NetC10_1: C10.1 R4.1 R9.2 U1.7 | length 2237.5
  Top Layer w10: C10.1@2052.37,1331.13 C10.1@2040,1343.5 ; U1.7@2184.21,1353 2184.21,1332.21 2174,1322 2123.5,1322 R9.2@2103,1342.5 2102,1343.5 C10.1@2040,1343.5 ; R4.1@2934.5,709 2912.5,731 2257.63,731 2132.63,606 1895.37,606 1743.46,757.92 1743.46,765.54 1721,788 1721,1024.5 C10.1@2040,1343.5
NetC10_2: C10.2 R5.2 R9.1 U1.6 | length 297.5
  Top Layer w10: R5.2@1970.5,1403 2100.5,1403 R9.1@2103,1405.5 2126.5,1429 2201,1429 2209.8,1420.2 U1.6@2209.8,1376.4
NetC12_1: C12.1 R13.1 R14.2 R15.1 | length 208.2
  Top Layer w10: C12.1@2299,1628.5 2295.98,1625.49 R13.1@2295.98,1558.7 2296.18,1558.5 R15.1@2363,1558.5 R14.2@2363,1628.5
NetC15_1: C15.1 R15.2 R21.2 U1.3 | length 381.2
  Top Layer w10: U1.3@2286.57,1376.4 2286.57,1431.57 2305,1450 2388,1450 2403,1465 2403,1491 ; R15.2@2363,1495.5 2398.5,1495.5 2403,1491 ; C15.1@2442.5,1585 2442.5,1520 R21.2@2443.5,1519 2415,1519 2403,1507 2403,1491
NetC16_1: C16.1 R16.1 R22.2 U1.1 | length 984.1
  Top Layer w10: U1.1@2337.75,1376.4 2364.6,1376.4 R22.2@2421.3,1319.7 ; R22.2@2426,1320.5 2489,1320.5 C16.1@2490,1321.5 2772.5,1321.5 2805,1289 v1(2805,1083) ; v1(2842,1007) 2842,978.06 2913.06,907 R16.1@2970.5,907
  Bottom Layer w10: v1(2805,1083) 2805,1044 v1(2842,1007)
NetC16_2: C16.2 R17.2 R22.1 U1.2 | length 367.4
  Top Layer w10: U1.2@2312.16,1376.4 2312.16,1416.16 2328,1432 2421.5,1432 ; R17.2@2444.5,1455 2421.5,1432 ; 2421.5,1432 2421.5,1387.99 R22.1@2426,1383.5 ; R22.1@2426,1383.5 2427,1384.5 C16.2@2490,1384.5 2489,1383.5 R22.1@2426,1383.5
NetC21_1: C21.1 R25.2 R28.2 U1.12 | length 393.6
  Top Layer w10: U1.12@2286.57,1152 2286.57,1101.61 2310.98,1077.2 2389.48,1077.2 R25.2@2430.48,1036.2 2498.48,968.2 R28.2@2503.49,968.2 C21.1@2503.49,897.2
NetC22_1: C22.1 R26.1 R29.2 U1.14 | length 872
  Top Layer w10: U1.14@2337.75,1152 2337.75,1197.97 2352.48,1212.7 C22.1@2490.8,1212.7 ; C22.1@2491,1212.5 C22.1@2490.8,1212.7 ; v1(2759,1088) 2634.3,1212.7 C22.1@2490.8,1212.7 ; v1(2812,974) 2812,936.5 R26.1@2934.5,814
  Bottom Layer w10: v1(2759,1088) 2759,1027 v1(2812,974)
NetC22_2: C22.2 R27.2 R29.1 U1.13 | length 360.3
  Top Layer w10: U1.13@2312.16,1152 2312.16,1113.02 2323.98,1101.2 2377.7,1101.2 R29.1@2426,1149.5 ; R29.1@2441.98,1149.7 2504.98,1149.7 2505.98,1150.7 2505.98,1034.7 R27.2@2504.49,1033.2
NetC23_2: C23.2 C65.2 R30.1 R32.1 U4.3 | length 715.1
  Top Layer w10: v1(3110,2100) 3110,2159.91 R30.1@3111,2160.91
  Top Layer w20: C65.2@3482,2163 C65.2@3485.5,2159.5
  Top Layer w30: U4.3@3452,2272.73 3452,2193 C65.2@3482,2163 ; R32.1@3460.91,1987 3482,2008.09 C23.2@3482,2074 ; v1(3485.5,2115.5) C65.2@3485.5,2159.5
  Bottom Layer w10: v1(3110,2100) 3116,2094 3464,2094 v1(3485.5,2115.5)
NetC28_1: C28.1 D9.1 U4.8 | length 274.4
  Top Layer w20: D9.1@3233,2432.74 3293.26,2493 3348.27,2493 U4.8@3352,2489.27 3352,2587 C28.1@3374,2609
NetC29_1: C29.1 R35.2 R112.1 U4.1 | length 469.1
  Top Layer w10: R112.1@3204,2175.5 3166.5,2138 3166.5,2057.5 3183.5,2040.5 R35.2@3270,2040.5
  Top Layer w15: C29.1@3268,2175.5 3268,2202.02 3287.98,2222 3335,2222 3352,2239 U4.1@3352,2272.73
  Top Layer w20: R112.1@3204,2175.5 3268,2175.5 C29.1@3269,2174.5
NetC30_1: C30.1 R36.2 R113.1 U4.2 | length 402.7
  Top Layer w10: R36.2@3337,2040.5 3419.5,2040.5 3438,2059 3438,2136.5 C30.1@3402,2172.5
  Top Layer w15: R113.1@3337,2173.5 3401,2173.5 C30.1@3402,2172.5 U4.2@3402,2272.73
NetC32_2: C32.2 C66.2 R40.1 R42.1 U5.3 | length 758.3
  Top Layer w10: v1(2063,2096) 2063,2153.91 2064,2154.91 R40.1@2063,2155.91
  Top Layer w30: U5.3@2406,2270.34 2406,2195 C66.2@2439,2162 v1(2439,2122) 2439,2073 C32.2@2438,2072 R42.1@2438,1996.5 ; R42.1@2439.5,1995 R42.1@2438,1996.5 ; R42.1@2439.91,1978 2438,1979.91 R42.1@2438,1996.5
  Bottom Layer w10: v1@2062,2095 2412,2095 v1(2439,2122)
NetC34_1: C34.1 D12.1 U5.8 | length 257.8
  Top Layer w20: D12.1@2192,2432.74 2246.13,2486.87 U5.8@2306,2486.87 2306,2587 C34.1@2321,2602
NetC35_1: C35.1 R50.2 R114.1 U5.1 | length 478.1
  Top Layer w10: R114.1@2151.3,2174.5 2112.29,2135.49 2112.29,2120.7 2108,2116.41 2108,2070 2138.5,2039.5 R50.2@2220,2039.5
  Top Layer w15: R114.1@2151.3,2174.5 2152.3,2173.5 C35.1@2219.3,2173.5 2219.3,2202.3 2237,2220 2288,2220 2306,2238 U5.1@2306,2270.34
NetC36_1: C36.1 R54.2 R115.1 U5.2 | length 410.6
  Top Layer w10: R54.2@2289,2040.5 2374.5,2040.5 2394,2060 2394,2135.8 C36.1@2357.3,2172.5
  Top Layer w15: R115.1@2286.3,2173.5 2287.3,2172.5 C36.1@2357.3,2172.5 2356,2173.8 U5.2@2356,2270.34
NetC38_2: C38.2 C67.2 R59.1 R61.1 U6.3 | length 818.7
  Top Layer w10: v1(1026,2085) R59.1@1026,2160.91 ; C67.2@1385,2184.08 C67.2@1385.52,2184.6 ; C67.2@1385.52,2171.52 C67.2@1385.52,2184.6 ; v1(1387.02,2126) 1387.02,2136.9 1410.12,2160 1387.02,2183.1 C67.2@1385.52,2184.6
  Top Layer w30: U6.3@1361.52,2276.34 1361.52,2208.6 C67.2@1385.52,2184.6 ; C38.2@1386,2082 1386.91,2081.09 R61.1@1386.91,1989 ; C38.2@1387.02,2100.6 v1(1387.02,2126) ; v1@1387.02,2136.9 C67.2@1387.02,2183.1
  Bottom Layer w10: v1(1026,2085) 1046,2105 1366.02,2105 v1(1387.02,2126) v1@1393,2126
NetC41_1: C41.1 D15.1 U6.8 | length 263
  Top Layer w20: D15.1@1144,2432.74 1150.24,2432.74 1210.37,2492.87 U6.8@1261.52,2492.87 ; D15.1@1150,2426.74 D15.1@1156.7,2420.04 ; U6.8@1261.52,2477.52 U6.8@1261.52,2492.87 ; C41.1@1261.52,2588.6 U6.8@1261.52,2492.87
NetC42_1: C42.1 R65.2 R116.1 U6.1 | length 452.4
  Top Layer w10: R116.1@1115,2181.5 1114.33,2181.5 1078.43,2145.59 1078.43,2075.17 1086,2067.6 1086,2066 1107.5,2044.5 R65.2@1185,2044.5
  Top Layer w15: C42.1@1178.52,2181.1 1178.52,2181.52 1222,2225 1251,2225 1261.52,2235.52 U6.1@1261.52,2276.34
  Top Layer w20: R116.1@1115,2181.5 1115.4,2181.1 C42.1@1178.52,2181.1
NetC43_1: C43.1 R69.1 R70.2 | length 160.8
  Top Layer w10: R70.2@3886.5,1363 3972.01,1363 R69.1@3972.5,1363.5 3972.5,1291 C43.1@3971,1289.5
NetC43_2: C43.2 R66.2 R67.1 | length 355
  Top Layer w10: R66.2@3887.5,1290 3887.5,1246.5 3907.5,1226.5 C43.2@3971,1226.5 4031.5,1287 4107,1287 R67.1@4148.5,1245.5
NetC45_1: C45.1 R71.2 R117.1 U6.2 | length 389.7
  Top Layer w10: R71.2@1249,2043.5 1317.5,2043.5 1342,2068 1342,2147.5 R117.1@1308,2181.5
  Top Layer w15: R117.1@1311.52,2185.02 U6.2@1311.52,2276.34
  Top Layer w20: C45.1@1245.52,2181.1 1307.6,2181.1 R117.1@1308,2181.5 R117.1@1311.52,2185.02
NetC47_2: C47.2 C48.2 U8.43 | length 232.7
  Top Layer w10: C48.2@3366.5,1133 3366,1132.5 C47.2@3366,1055 3366,1046 3398.3,1013.7 U8.43@3398.3,913.9
NetC54_1: C54.1 R86.1 R87.2 U8.3 | length 1954.8
  Top Layer w10: R87.2@2345,216.5 2352.5,224 2362.5,214 v1(2388,214) ; v1(2388,384) 2794,384 2945,233 v1(2975,233) ; R86.1@3036.5,977 3061.5,977 C54.1@3118,920.5 3158.5,920.5 3188,891 3188,829 3200,817 U8.3@3242.1,817 3285,817 3311,791 3311,649 3187,525 3187,501 3150,464 3150,408 v1(3106,364)
  Bottom Layer w10: v1(2388,214) v1(2388,384) ; v1(2975,233) v1(3106,364)
NetC55_1: C55.1 C56.1 U8.32 | length 188.4
  Top Layer w10: U8.32@3574.1,777.6 3629.4,777.6 3642.5,764.5 C56.1@3678,764.5 3753.5,764.5 C55.1@3756,762
NetC57_1: C57.1 C58.1 R88.1 U8.11 | length 363
  Top Layer w10: R88.1@2969,523.5 3036.5,523.5 C57.1@3049,536 3083.5,570.5 C58.1@3124,570.5 3159.5,570.5 3173,584 3173,640 3192.4,659.4 U8.11@3242.1,659.4 U8.11@3241.5,660
NetC68_1: C68.1 R120.2 U8.10 | length 322.4
  Top Layer w15: R120.2@2996.5,640 2996.5,604.5 3009,592 3077.5,592 C68.1@3126.5,641 3164.6,679.1 U8.10@3242.1,679.1
NetD1_1: D1.1 D3.1 D4.1 R6.2 | length 461.5
  Top Layer w10: D1.1@2005.47,705 2002.47,708 D3.1@2002.47,913 2062.17,972.7 R6.2@2229.98,972.7
NetD2_1: D2.1 D7.1 R8.1 | length 1965.8
  Top Layer w10: D7.1@1509.53,1026.53 D7.1@1499,1026.53 1554.47,1082 v1(1734,1082) ; v1(1827,1082) 1956.53,1082 D2.1@1965.53,1073 v1(2007,1073) ; v1(2101,942) 2101,865 2152,814 2806,814 v1(2845,853) ; v1(2923,931) 2923,1057 v1(2924,1058) ; R8.1@2975,1139.5 3006,1108.5 v1(3006,1095)
  Bottom Layer w10: v1(1734,1082) v1(1827,1082) ; v1(2007,1073) 2101,979 v1(2101,942) ; v1(2845,853) v1(2923,931) ; v1(2924,1058) 2969,1058 v1(3006,1095)
NetD2_2: D2.2 U1.8 | length 149.9
  Top Layer w10: D2.2@2094.47,1073 2152,1073 2184.21,1105.21 U1.8@2184.21,1152
NetD5_2: D5.2 D6.2 D8.2 R11.2 | length 271.7
  Top Layer w10: R11.2@1579.5,898 1640.53,898 D8.2@1643.53,895 ; D6.2@1642.53,1000 1643.53,999 D8.2@1643.53,895 ; D5.2@1643.53,794 D8.2@1643.53,895
NetD7_2: D7.2 R12.1 U3.4 | length 238.7
  Top Layer w10: R12.1@1360.5,1236 1366.4,1230.09 U3.4@1366.4,1139.13 1482.67,1139.13 D7.2@1499,1155.47
NetD9_2: D9.2 R30.2 | length 122.1
  Top Layer w40: R30.2@3111,2275.09 3232.83,2275.09 D9.2@3233,2275.26
NetD10_1: D10.1 R33.1 U4.7 | length 339.6
  Top Layer w20: D10.1@3215.47,2546 3220.47,2541 v1(3308,2541) ; U4.7@3402,2489.27 v1(3402,2542)
  Top Layer w30: D10.1@3215.47,2546 3215.47,2630.38 R33.1@3225,2639.91
  Bottom Layer w20: v1(3308,2541) 3309,2542 v1(3402,2542)
NetD10_2: D10.2 R31.1 | length 105.4
  Top Layer w30: D10.2@3086.53,2546 3086.53,2605.44 R31.1@3119,2637.91
NetD11_1: D11.1 R37.1 U4.5 | length 231.4
  Top Layer w30: U4.5@3502,2489.27 3502,2510 3527,2535 3609.53,2535 ; D11.1@3609.53,2488 3609.53,2535 ; R37.1@3614,2578.91 3609.53,2574.44 3609.53,2535
NetD11_2: D11.2 R38.1 | length 99
  Top Layer w30: R38.1@3719,2578.91 3719,2507.47 D11.2@3738.47,2488
NetD12_2: D12.2 R40.2 | length 131.1
  Top Layer w40: R40.2@2063,2270.09 2068.17,2275.26 D12.2@2192,2275.26
NetD13_1: D13.1 R45.1 U5.7 | length 326.5
  Top Layer w20: D13.1@2176.47,2545 2185.47,2536 v1(2262,2536) ; U5.7@2356,2486.87 v1(2356,2534)
  Top Layer w30: D13.1@2176.47,2545 2176.47,2625.38 R45.1@2187,2635.91
  Bottom Layer w20: v1(2262,2536) 2264,2534 v1(2356,2534)
NetD13_2: D13.2 R41.1 | length 103.7
  Top Layer w30: D13.2@2047.53,2545 2047.53,2608.44 R41.1@2076,2636.91
NetD14_1: D14.1 R55.1 U5.5 | length 256.5
  Top Layer w20: D14.1@2571.53,2488 D14.1@2581,2497.47
  Top Layer w30: U5.5@2456,2486.87 2456,2511 2472,2527 2571.53,2527 ; D14.1@2571.53,2488 2571.53,2527 ; R55.1@2581,2580.91 2571.53,2571.44 2571.53,2527
NetD14_2: D14.2 R57.1 | length 99.3
  Top Layer w30: R57.1@2685,2580.91 2685,2503.47 D14.2@2700.47,2488
NetD15_2: D15.2 R59.2 | length 123.3
  Top Layer w40: R59.2@1021,2276.09 1143.17,2276.09 D15.2@1144,2275.26
NetD16_1: D16.1 R62.1 U6.7 | length 326.3
  Top Layer w20: v1(1310.52,2542.6) 1310.52,2493.87 U6.7@1311.52,2492.87 U6.7@1312.52,2493.87
  Top Layer w30: R62.1@1134,2631.6 1127.47,2625.07 D16.1@1127.47,2544 1128.47,2545 v1(1215,2545)
  Bottom Layer w30: v1(1215,2545) 1308.12,2545 v1(1310.52,2542.6)
NetD16_2: D16.2 R60.1 | length 99.7
  Top Layer w30: D16.2@998.53,2544 998.53,2609.13 R60.1@1023,2633.6
NetD17_1: D17.1 R72.1 U6.5 | length 253.1
  Top Layer w30: U6.5@1411.52,2492.87 1411.52,2512.52 1441,2542 1540.68,2542 ; D17.1@1540.22,2499.5 1540.68,2499.97 1540.68,2542 ; R72.1@1540.68,2591.41 1540.68,2542
NetD17_2: D17.2 R75.1 | length 102
  Top Layer w30: R75.1@1644.68,2591.41 1644.68,2523.97 D17.2@1669.15,2499.5
NetD18_1: D18.1 R84.2
NetD19_1: D19.1 R85.2 | length 73.2
  Top Layer w10: D19.1@907,1029.5 975.99,1029.5 R85.2@979,1026.5
NetD20_1: D20.1 U8.48 | length 221
  Top Layer w10: D20.1@3162.5,1053 3228,987.5 3228,943 3257.1,913.9 U8.48@3299.8,913.9
NetD20_2: D20.2 R82.1 | length 61.4
  Top Layer w10: R82.1@3038.5,1054 3098.5,1054 D20.2@3099.5,1053
NetD21_2: D21.2 J6.1 | length 6.3
  Top Layer w30: J6.1@135.53,827.11 J6.1@140,831.57
NetQ4_3: Q4.3 R43.1 R44.1 | length 1086.6
  Top Layer w10: v1(1804,2563) 1804,1726 1835,1695 R43.1@1835,1598.5
  Bottom Layer w10: v1(1804,2563) 1827,2586 R44.1@1827,2642.05
  Bottom Layer w30: R44.1@1856.05,2647 1876,2647 R44.1@1875.5,2647.5
NetQ5_3: Q5.3 R51.1 R52.1 | length 1230.1
  Top Layer w10: R51.1@2703.5,1520 2745.87,1520 2798,1572.13 2798,2536 2817,2555 v1(2841,2555)
  Bottom Layer w10: v1(2841,2555) 2868,2582 R52.1@2868,2643.05
NetQ6_3: Q6.3 R46.2 R48.1 | length 2634.9
  Top Layer w10: R46.2@2760.5,969 2761.63,969 2856,1063.37 2856,1755 2909,1808 3758,1808 3907,1957 v1(3907,2556)
  Bottom Layer w10: v1(3907,2556) R48.1@3907,2631.05
NetR6_1: R6.1 U1.10 | length 118.5
  Top Layer w10: R6.1@2229.98,1035.7 2235.39,1041.11 U1.10@2235.39,1152
NetR10_2: R10.2 R11.1 U3.3 | length 250.1
  Top Layer w10: U3.3@1366.4,1030.87 1367.5,1029.77 R10.2@1367.5,953 1422.5,898 R11.1@1516.5,898
NetR63_2: R63.2 R70.1 RT1.1 | length 1745.5
  Top Layer w10: R63.2@3737.5,1361 3739.5,1363 R70.1@3823.5,1363 3823.5,1599.5 3932,1708 4054,1708 4345.47,1999.47 RT1.1@4347.47,2734
NetR66_1: R66.1 R74.1 RT1.2 | length 1974.8
  Top Layer w10: R74.1@3738.5,1291 3739.5,1290 R66.1@3824.5,1290 3824.5,1250.5 v1(3851,1224) ; v1(3851,1431) 3851,1596 3943,1688 4066,1688 4371.04,1993.04 4373,2689.11 4406.49,2722.42 RT1.2@4406.53,2734
  Bottom Layer w10: v1(3851,1224) v1(3851,1431)
NetR67_2: R67.2 R77.1 U7.4 | length 150.9
  Top Layer w10: R77.1@4211.5,1181 R67.2@4211.5,1245.5 4231.13,1265.13 U7.4@4231.13,1323.79
NetR68_1: R68.1 R77.2 U7.1 | length 1387
  Top Layer w10: R68.1@3640.5,414 3850,414 4089,653 4089,966 v1(4087,968) ; v1(4082.6,1249) 4082.6,1246.91 R77.2@4148.5,1181 4087,1119.5 v1(4087,1053) ; v1(4082.6,1398.6) U7.1@4122.86,1398.6
  Bottom Layer w10: v1(4082.6,1249) v1(4082.6,1398.6) ; v1(4087,968) v1(4087,1053)
NetR69_2: R69.2 R73.1 U7.3 | length 183
  Top Layer w10: R73.1@4036,1442.5 4035.5,1442 R69.2@4035.5,1363.5 4075.2,1323.79 U7.3@4122.86,1323.79
NetR78_2: R78.2 R79.1 R81.2 | length 2083.7
  Top Layer w10: R81.2@1855,235.1 2012.1,235.1 2059,282 2744,282 2905,121 v1(3406,121) ; v1(3483,320) 3483,368.5 R79.1@3509,394.5
  Top Layer w20: R78.2@1725,234 1726.1,235.1 R81.2@1855,235.1
  Bottom Layer w10: v1(3406,121) 3483,198 v1(3483,320)
NetR80_1: R80.1 R83.2 | length 212.2
  Bottom Layer w50: R83.2@353.91,2737 353.91,2920.83 R80.1@374,2940.91
NetR91_1: R91.1 R95.2 | length 572.6
  Top Layer w10: R95.2@772,2595.09 772,2661 955,2844 R91.1@955,3091.91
